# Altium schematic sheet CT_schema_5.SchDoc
size 258 x 163 mm
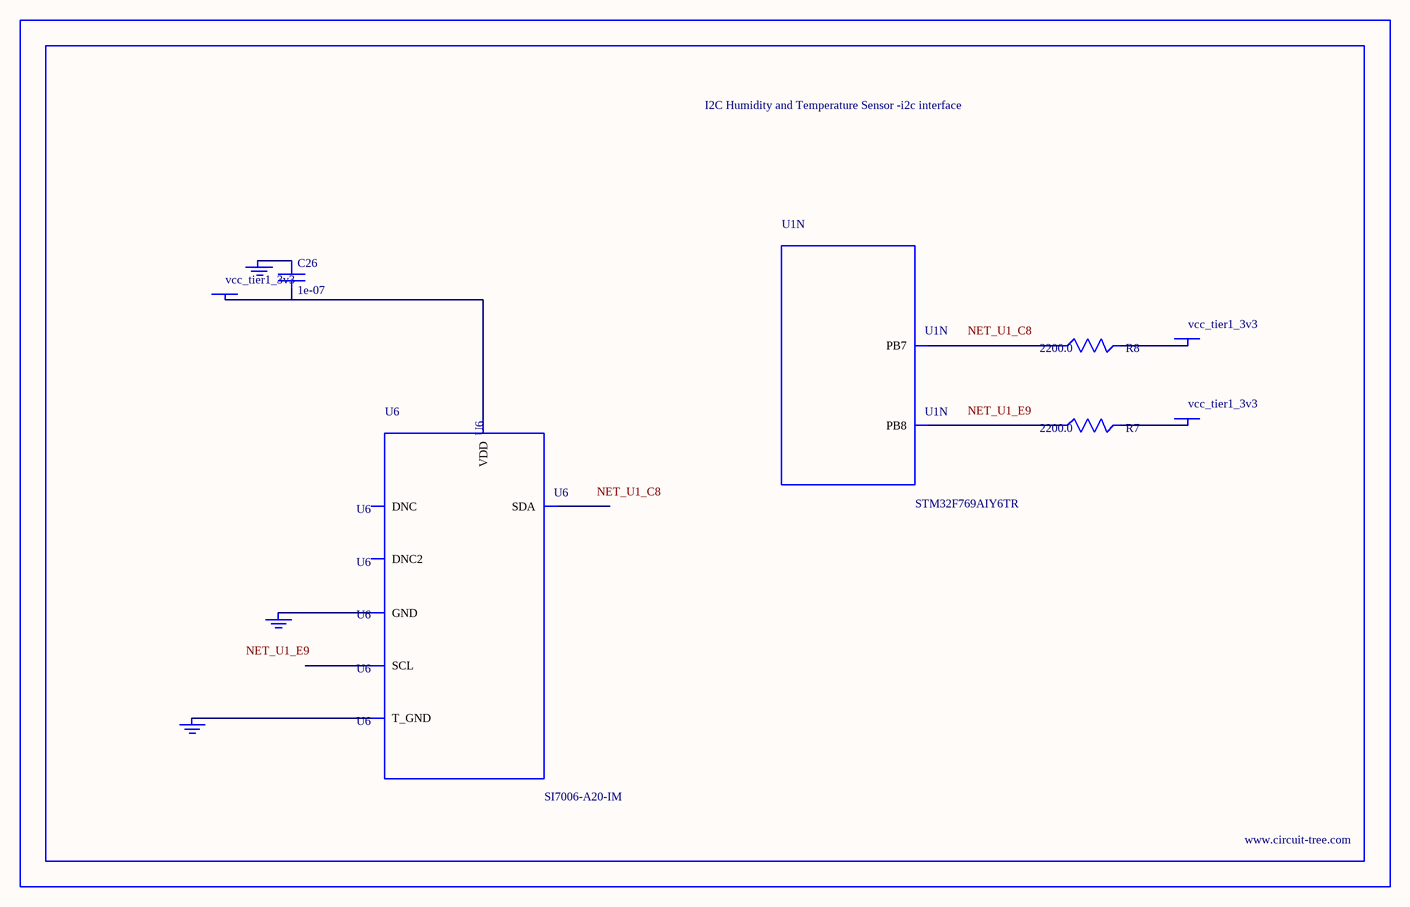
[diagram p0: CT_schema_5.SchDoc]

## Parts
BORDER4  (no value)
C26  1e-07  [C0402]
GND_INSTANCE_4_0  (no value)
GND_INSTANCE_4_1  (no value)
GND_INSTANCE_4_2  (no value)
POWER_INSTANCE_4_0  vcc_tier1_3v3
POWER_INSTANCE_4_1  vcc_tier1_3v3
POWER_INSTANCE_4_2  vcc_tier1_3v3
R7  2200.0  [R0603]
R8  2200.0  [R0603]
U1  STM32F769AIY6TR  [WLCSP180]  (part N of 15)
U6  SI7006-A20-IM  [DFN-6]

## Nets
NetC26_1: C26.1 GND_INSTANCE_4_0.0(GND)
NetC26_2: C26.2 POWER_INSTANCE_4_0.0(PWR) U6.5(VDD)
NetGND_INSTANCE_4_1_0: GND_INSTANCE_4_1.0(GND) U6.7(T_GND)
NetGND_INSTANCE_4_2_0: GND_INSTANCE_4_2.0(GND) U6.2(GND)
NetPOWER_INSTANCE_4_1_0: POWER_INSTANCE_4_1.0(PWR) R8.2
NetPOWER_INSTANCE_4_2_0: POWER_INSTANCE_4_2.0(PWR) R7.2
NetR7_1: R7.1 U1.E9(PB8)
NetR8_1: R8.1 U1.C8(PB7)

Not connected (* = marked no-connect by the designer): U6 1(SDA) 3(DNC) 4(DNC2) 6(SCL)

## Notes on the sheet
- Labels drawn without touching a wire or pin: NET_U1_C8, NET_U1_E9

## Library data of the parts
BORDER4 = BORDER_PAGE4
C26 = C0402C104K3RACTU
GND_INSTANCE_4_0-GND_INSTANCE_4_2 = GND
POWER_INSTANCE_4_0-POWER_INSTANCE_4_2 = PWR
R7 R8 = RC0603JR-072K2L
